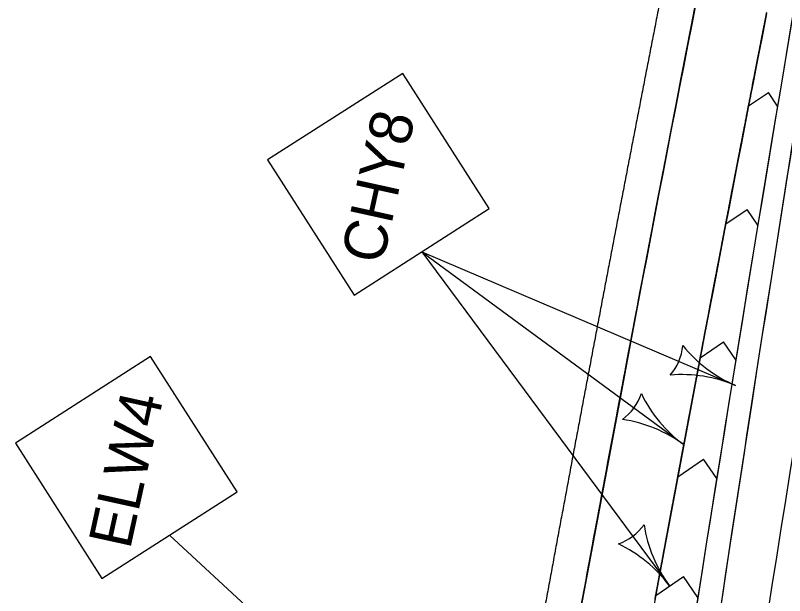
# Model space of a CAD drawing. Extents: x 14104283 to 14120882, y 8635219 to 8671666.
# Drawn here: x 14107883.7 to 14108013.1, y 8640340.4 to 8640438 of the extents above; entities that cross this region are included whole.
import ezdxf

# ---------------------------------------------------------------- set-up
doc = ezdxf.new("R2010")
doc.units = 0
for name, color, linetype in [('dsnPaintPlaceBrokenLineWhite', 7, 'Continuous'), ('dsnPaintPlaceChannelizingLaneWhite', 7, 'Continuous'), ('dsnPaintPlaceEdgeLineRightWhite', 7, 'Continuous'), ('dsnShadingPaved', 7, 'Continuous'), ('dsnStdLabel', 7, 'Continuous'), ('dsnStgShadingPrevPav', 7, 'Continuous')]:
    doc.layers.add(name, color=color, linetype=linetype)

msp = doc.modelspace()

# ---------------------------------------------------------------- linework, layer by layer
at = {"layer": 'dsnPaintPlaceBrokenLineWhite'}
msp.add_arc((14117394.14, 8638857.08), 9500, 167.610212, 171.325989, dxfattribs=at)
at = {"layer": 'dsnPaintPlaceChannelizingLaneWhite'}
for p, q in [((14108006.99, 8640422.76), (14108010.34, 8640425.01)), ((14108011.88, 8640422.72), (14108010.34, 8640425.01)), ((14108003.16, 8640402.9), (14108006.75, 8640405.34)), ((14108008.56, 8640402.67), (14108006.75, 8640405.34)), ((14107998.87, 8640380.39), (14108002.8, 8640383.07)), ((14108004.86, 8640380.03), (14108002.78, 8640383.07)), ((14107995.1, 8640360.4), (14107999.42, 8640363.36)), ((14108001.65, 8640360.1), (14107999.42, 8640363.36)), ((14107991.39, 8640340.45), (14107996.03, 8640343.65)), ((14107998.47, 8640340.1), (14107996.03, 8640343.65))]:
    msp.add_line(p, q, dxfattribs=at)
for centre, radius, start, end in [((14117394.14, 8638857.08), 9512, 169.444425, 171.325989), ((14117350.61, 8638608.07), 9518.2, 168.915826, 170.320937)]:
    msp.add_arc(centre, radius, start, end, dxfattribs=at)
at = {"layer": 'dsnPaintPlaceEdgeLineRightWhite'}
msp.add_arc((14117350.61, 8638608.07), 9530.2, 168.915826, 170.320937, dxfattribs=at)
at = {"layer": 'dsnShadingPaved'}
for centre, radius, start, end in [((14117394.14, 8638857.08), 9512, 167.610212, 171.325989), ((14117394.14, 8638857.08), 9500, 167.610212, 171.325989), ((14117350.61, 8638608.07), 9530.2, 168.915826, 170.320937), ((14117350.61, 8638608.07), 9518.2, 168.915826, 170.320937)]:
    msp.add_arc(centre, radius, start, end, dxfattribs=at)
at = {"layer": 'dsnStdLabel'}
for p, q in [((14107952.01, 8640398.19), (14107996.08, 8640365.81)), ((14107952.01, 8640398.19), (14108004.82, 8640375.74)), ((14107952.01, 8640398.19), (14107993.71, 8640342.05)), ((14107909.59, 8640350.58), (14107971.39, 8640293.53))]:
    msp.add_line(p, q, dxfattribs=at)
for points in [[(14107940.63, 8640390.92), (14107963.38, 8640405.47), (14107948.83, 8640428.21), (14107926.08, 8640413.66)], [(14107898.22, 8640343.3), (14107920.97, 8640357.85), (14107906.42, 8640380.6), (14107883.67, 8640366.05)]]:
    msp.add_lwpolyline(points, close=True, dxfattribs=at)
for centre, radius, start, end in [((14107987.11, 8640383.26), 8.86, 319.2327, 354.7011), ((14108013.8, 8640396.86), 22.95, 218.8957, 246.967), ((14107995.84, 8640354.62), 22.95, 66.9669, 95.0381), ((14107980.57, 8640377.2), 8.86, 305.9579, 341.4263), ((14108009.67, 8640384.3), 22.95, 205.6209, 233.6922), ((14107982.49, 8640347.31), 22.95, 53.6921, 81.7633), ((14107982.23, 8640357.5), 8.86, 288.8714, 324.3398), ((14108012.13, 8640355.73), 22.95, 188.5344, 216.6057), ((14107975.28, 8640328.36), 22.95, 36.6055, 64.6768)]:
    msp.add_arc(centre, radius, start, end, dxfattribs=at)
at = {"layer": 'dsnStgShadingPrevPav'}
for radius, start, end in [(9488, 167.610212, 172.222077), (9512, 169.413861, 172.222077), (9488, 169.413861, 172.222077), (9512, 170.574102, 171.702544)]:
    msp.add_arc((14117407.82, 8638919.35), radius, start, end, dxfattribs=at)
for points, degree in [([(14108040.07, 8640670.33), (14108039.11, 8640666.01), (14108035.79, 8640651.03), (14108029.85, 8640623.7), (14108025.19, 8640602.04), (14108020.26, 8640578.84), (14108015.47, 8640556.04), (14108010.72, 8640533.12), (14108006.03, 8640510.22), (14108001.39, 8640487.29), (14107996.81, 8640464.36), (14107992.28, 8640441.41), (14107987.82, 8640418.46), (14107983.4, 8640395.49), (14107979.05, 8640372.51), (14107974.75, 8640349.53), (14107970.51, 8640326.51), (14107966.33, 8640303.59), (14107962.15, 8640280.24), (14107958.29, 8640258.43), (14107953.48, 8640230.88), (14107950.9, 8640215.75), (14107950.15, 8640211.39)], 2), ([(14107956.07, 8640210.37), (14107957.38, 8640218.06), (14107960.02, 8640233.43), (14107964.04, 8640256.47), (14107968.11, 8640279.5), (14107972.24, 8640302.51), (14107976.42, 8640325.52), (14107980.66, 8640348.51), (14107984.96, 8640371.49), (14107989.32, 8640394.46), (14107993.73, 8640417.41), (14107998.19, 8640440.35), (14108002.71, 8640463.28), (14108007.29, 8640486.2), (14108011.92, 8640509.1), (14108016.61, 8640531.99), (14108021.36, 8640554.87), (14108026.16, 8640577.73), (14108031.01, 8640600.58), (14108035.93, 8640623.41), (14108040.89, 8640646.24), (14108044.25, 8640661.44), (14108045.92, 8640669.04)], 3), ([(14107995.51, 8640426.59), (14107996.26, 8640430.41), (14107997, 8640434.24), (14107997.75, 8640438.06)], 2), ([(14108010.05, 8640438.44), (14108009.9, 8640437.67), (14108009.75, 8640436.91), (14108009.6, 8640436.15)], 2), ([(14108009.6, 8640436.15), (14108009.75, 8640436.91), (14108009.9, 8640437.67), (14108010.05, 8640438.44)], 2), ([(14108009.37, 8640435), (14108009.15, 8640433.86), (14108008.93, 8640432.71), (14108008.7, 8640431.56)], 2), ([(14108008.7, 8640431.56), (14108008.93, 8640432.71), (14108009.15, 8640433.86), (14108009.37, 8640435)], 2), ([(14108009.6, 8640436.15), (14108009.52, 8640435.76), (14108009.45, 8640435.38), (14108009.37, 8640435)], 2), ([(14108009.37, 8640435), (14108009.45, 8640435.38), (14108009.52, 8640435.76), (14108009.6, 8640436.15)], 2), ([(14108008.7, 8640431.56), (14108008.63, 8640431.18), (14108008.55, 8640430.8), (14108008.48, 8640430.42)], 2), ([(14108008.48, 8640430.42), (14108008.55, 8640430.8), (14108008.63, 8640431.18), (14108008.7, 8640431.56)], 2), ([(14108008.48, 8640430.42), (14108008.4, 8640430.04), (14108008.33, 8640429.65), (14108008.26, 8640429.27)], 2), ([(14108008.26, 8640429.27), (14108008.33, 8640429.65), (14108008.4, 8640430.04), (14108008.48, 8640430.42)], 2), ([(14108008.26, 8640429.27), (14108008.18, 8640428.89), (14108008.11, 8640428.51), (14108008.03, 8640428.13)], 2), ([(14108008.03, 8640428.13), (14108008.11, 8640428.51), (14108008.18, 8640428.89), (14108008.26, 8640429.27)], 2), ([(14108008.03, 8640428.13), (14108007.29, 8640424.31), (14108006.55, 8640420.49), (14108005.81, 8640416.67)], 2), ([(14108005.81, 8640416.67), (14108006.55, 8640420.49), (14108007.29, 8640424.31), (14108008.03, 8640428.13)], 2), ([(14107995.29, 8640425.44), (14107995.37, 8640425.82), (14107995.44, 8640426.21), (14107995.51, 8640426.59)], 2), ([(14107995.07, 8640424.29), (14107995.14, 8640424.68), (14107995.22, 8640425.06), (14107995.29, 8640425.44)], 2), ([(14107994.85, 8640423.15), (14107994.92, 8640423.53), (14107994.99, 8640423.91), (14107995.07, 8640424.29)], 2), ([(14107994.4, 8640420.85), (14107994.55, 8640421.62), (14107994.7, 8640422.38), (14107994.85, 8640423.15)], 2), ([(14107994.18, 8640419.7), (14107994.25, 8640420.09), (14107994.33, 8640420.47), (14107994.4, 8640420.85)], 2), ([(14107993.73, 8640417.41), (14107993.88, 8640418.17), (14107994.03, 8640418.94), (14107994.18, 8640419.7)], 2), ([(14107992.63, 8640411.67), (14107993, 8640413.58), (14107993.36, 8640415.5), (14107993.73, 8640417.41)], 2), ([(14108005.59, 8640415.52), (14108005.36, 8640414.38), (14108005.14, 8640413.23), (14108004.92, 8640412.09)], 2), ([(14108004.92, 8640412.09), (14108005.14, 8640413.23), (14108005.36, 8640414.38), (14108005.59, 8640415.52)], 2), ([(14108005.81, 8640416.67), (14108005.73, 8640416.29), (14108005.66, 8640415.91), (14108005.59, 8640415.52)], 2), ([(14108005.59, 8640415.52), (14108005.66, 8640415.91), (14108005.73, 8640416.29), (14108005.81, 8640416.67)], 2), ([(14107991.52, 8640405.93), (14107991.89, 8640407.85), (14107992.26, 8640409.76), (14107992.63, 8640411.67)], 2), ([(14108004.92, 8640412.09), (14108004.77, 8640411.32), (14108004.63, 8640410.56), (14108004.48, 8640409.79)], 2), ([(14108004.48, 8640409.79), (14108004.63, 8640410.56), (14108004.77, 8640411.32), (14108004.92, 8640412.09)], 2), ([(14108004.48, 8640409.79), (14108004.18, 8640408.27), (14108003.89, 8640406.74), (14108003.6, 8640405.21)], 2), ([(14108003.6, 8640405.21), (14108003.89, 8640406.74), (14108004.18, 8640408.27), (14108004.48, 8640409.79)], 2), ([(14107991.3, 8640404.79), (14107991.38, 8640405.17), (14107991.45, 8640405.55), (14107991.52, 8640405.93)], 2), ([(14108003.6, 8640405.21), (14108003.3, 8640403.68), (14108003.01, 8640402.15), (14108002.72, 8640400.62)], 2), ([(14108002.72, 8640400.62), (14108003.01, 8640402.15), (14108003.3, 8640403.68), (14108003.6, 8640405.21)], 2), ([(14107990.42, 8640400.19), (14107990.72, 8640401.73), (14107991.01, 8640403.26), (14107991.3, 8640404.79)], 2), ([(14107989.54, 8640395.6), (14107989.84, 8640397.13), (14107990.13, 8640398.66), (14107990.42, 8640400.19)], 2), ([(14108002.72, 8640400.62), (14108002.28, 8640398.33), (14108001.84, 8640396.04), (14108001.4, 8640393.74)], 2), ([(14108001.4, 8640393.74), (14108001.84, 8640396.04), (14108002.28, 8640398.33), (14108002.72, 8640400.62)], 2), ([(14107989.33, 8640394.45), (14107989.4, 8640394.84), (14107989.47, 8640395.22), (14107989.54, 8640395.6)], 2), ([(14107989.11, 8640393.31), (14107989.18, 8640393.69), (14107989.25, 8640394.07), (14107989.33, 8640394.45)], 2), ([(14108001.4, 8640393.74), (14108001.33, 8640393.36), (14108001.25, 8640392.98), (14108001.18, 8640392.6)], 2), ([(14108001.18, 8640392.6), (14108001.25, 8640392.98), (14108001.33, 8640393.36), (14108001.4, 8640393.74)], 2), ([(14107988.23, 8640388.71), (14107988.52, 8640390.25), (14107988.81, 8640391.78), (14107989.11, 8640393.31)], 2), ([(14108001.18, 8640392.6), (14108001.03, 8640391.83), (14108000.89, 8640391.07), (14108000.74, 8640390.3)], 2), ([(14108000.74, 8640390.3), (14108000.89, 8640391.07), (14108001.03, 8640391.83), (14108001.18, 8640392.6)], 2), ([(14108000.74, 8640390.3), (14108000.6, 8640389.54), (14108000.45, 8640388.78), (14108000.31, 8640388.01)], 2), ([(14108000.31, 8640388.01), (14108000.45, 8640388.78), (14108000.6, 8640389.54), (14108000.74, 8640390.3)], 2), ([(14107987.58, 8640385.27), (14107987.79, 8640386.42), (14107988.01, 8640387.57), (14107988.23, 8640388.71)], 2), ([(14108000.31, 8640388.01), (14108000.02, 8640386.48), (14107999.72, 8640384.95), (14107999.43, 8640383.42)], 2), ([(14107999.43, 8640383.42), (14107999.72, 8640384.95), (14108000.02, 8640386.48), (14108000.31, 8640388.01)], 2), ([(14107987.36, 8640384.12), (14107987.43, 8640384.5), (14107987.5, 8640384.89), (14107987.58, 8640385.27)], 2), ([(14107986.92, 8640381.82), (14107987.07, 8640382.59), (14107987.21, 8640383.36), (14107987.36, 8640384.12)], 2), ([(14107999.43, 8640383.42), (14107999, 8640381.13), (14107998.56, 8640378.84), (14107998.13, 8640376.54)], 2), ([(14107998.13, 8640376.54), (14107998.56, 8640378.84), (14107999, 8640381.13), (14107999.43, 8640383.42)], 2), ([(14107986.05, 8640377.23), (14107986.34, 8640378.76), (14107986.63, 8640380.29), (14107986.92, 8640381.82)], 2), ([(14107985.84, 8640376.08), (14107985.91, 8640376.46), (14107985.98, 8640376.85), (14107986.05, 8640377.23)], 2), ([(14107985.19, 8640372.64), (14107985.4, 8640373.78), (14107985.62, 8640374.93), (14107985.84, 8640376.08)], 2), ([(14107998.13, 8640376.54), (14107998.06, 8640376.16), (14107997.99, 8640375.78), (14107997.91, 8640375.4)], 2), ([(14107997.91, 8640375.4), (14107997.99, 8640375.78), (14107998.06, 8640376.16), (14107998.13, 8640376.54)], 2), ([(14107997.91, 8640375.4), (14107997.55, 8640373.48), (14107997.19, 8640371.57), (14107996.83, 8640369.66)], 2), ([(14107996.83, 8640369.66), (14107997.19, 8640371.57), (14107997.55, 8640373.48), (14107997.91, 8640375.4)], 2), ([(14107984.97, 8640371.49), (14107985.04, 8640371.87), (14107985.12, 8640372.25), (14107985.19, 8640372.64)], 2), ([(14107984.32, 8640368.04), (14107984.54, 8640369.19), (14107984.76, 8640370.34), (14107984.97, 8640371.49)], 2), ([(14107996.83, 8640369.66), (14107996.62, 8640368.51), (14107996.4, 8640367.37), (14107996.18, 8640366.22)], 2), ([(14107996.18, 8640366.22), (14107996.4, 8640367.37), (14107996.62, 8640368.51), (14107996.83, 8640369.66)], 2), ([(14107983.25, 8640362.3), (14107983.6, 8640364.21), (14107983.96, 8640366.13), (14107984.32, 8640368.04)], 2), ([(14107995.97, 8640365.07), (14107995.9, 8640364.69), (14107995.82, 8640364.31), (14107995.75, 8640363.92)], 2), ([(14107995.75, 8640363.92), (14107995.82, 8640364.31), (14107995.9, 8640364.69), (14107995.97, 8640365.07)], 2), ([(14107996.18, 8640366.22), (14107996.11, 8640365.84), (14107996.04, 8640365.45), (14107995.97, 8640365.07)], 2), ([(14107995.97, 8640365.07), (14107996.04, 8640365.45), (14107996.11, 8640365.84), (14107996.18, 8640366.22)], 2), ([(14107995.75, 8640363.92), (14107995.68, 8640363.54), (14107995.61, 8640363.16), (14107995.54, 8640362.78)], 2), ([(14107995.54, 8640362.78), (14107995.61, 8640363.16), (14107995.68, 8640363.54), (14107995.75, 8640363.92)], 2), ([(14107995.54, 8640362.78), (14107995.32, 8640361.63), (14107995.11, 8640360.48), (14107994.89, 8640359.33)], 2), ([(14107994.89, 8640359.33), (14107995.11, 8640360.48), (14107995.32, 8640361.63), (14107995.54, 8640362.78)], 2), ([(14107982.39, 8640357.7), (14107982.67, 8640359.23), (14107982.96, 8640360.76), (14107983.25, 8640362.3)], 2), ([(14107994.89, 8640359.33), (14107994.68, 8640358.19), (14107994.46, 8640357.04), (14107994.25, 8640355.89)], 2), ([(14107994.25, 8640355.89), (14107994.46, 8640357.04), (14107994.68, 8640358.19), (14107994.89, 8640359.33)], 2), ([(14107981.96, 8640355.4), (14107982.1, 8640356.17), (14107982.24, 8640356.93), (14107982.39, 8640357.7)], 2), ([(14107981.74, 8640354.25), (14107981.81, 8640354.64), (14107981.89, 8640355.02), (14107981.96, 8640355.4)], 2), ([(14107994.03, 8640354.74), (14107993.96, 8640354.36), (14107993.89, 8640353.98), (14107993.82, 8640353.6)], 2), ([(14107993.82, 8640353.6), (14107993.89, 8640353.98), (14107993.96, 8640354.36), (14107994.03, 8640354.74)], 2), ([(14107994.25, 8640355.89), (14107994.18, 8640355.51), (14107994.11, 8640355.13), (14107994.03, 8640354.74)], 2), ([(14107994.03, 8640354.74), (14107994.11, 8640355.13), (14107994.18, 8640355.51), (14107994.25, 8640355.89)], 2), ([(14107981.53, 8640353.1), (14107981.6, 8640353.49), (14107981.67, 8640353.87), (14107981.74, 8640354.25)], 2), ([(14107993.82, 8640353.6), (14107993.75, 8640353.21), (14107993.68, 8640352.83), (14107993.61, 8640352.45)], 2), ([(14107993.61, 8640352.45), (14107993.68, 8640352.83), (14107993.75, 8640353.21), (14107993.82, 8640353.6)], 2), ([(14107981.1, 8640350.81), (14107981.24, 8640351.57), (14107981.39, 8640352.34), (14107981.53, 8640353.1)], 2), ([(14107993.61, 8640352.45), (14107993.53, 8640352.06), (14107993.46, 8640351.68), (14107993.39, 8640351.3)], 2), ([(14107993.39, 8640351.3), (14107993.46, 8640351.68), (14107993.53, 8640352.06), (14107993.61, 8640352.45)], 2), ([(14107993.39, 8640351.3), (14107993.11, 8640349.77), (14107992.82, 8640348.24), (14107992.54, 8640346.71)], 2), ([(14107992.54, 8640346.71), (14107992.82, 8640348.24), (14107993.11, 8640349.77), (14107993.39, 8640351.3)], 2), ([(14107980.67, 8640348.51), (14107980.74, 8640348.89), (14107980.82, 8640349.27), (14107980.89, 8640349.66)], 2), ([(14107980.89, 8640349.66), (14107980.96, 8640350.04), (14107981.03, 8640350.42), (14107981.1, 8640350.81)], 2), ([(14107980.46, 8640347.36), (14107980.53, 8640347.74), (14107980.6, 8640348.12), (14107980.67, 8640348.51)], 2), ([(14107979.4, 8640341.61), (14107979.75, 8640343.53), (14107980.1, 8640345.44), (14107980.46, 8640347.36)], 2), ([(14107992.54, 8640346.71), (14107992.11, 8640344.41), (14107991.69, 8640342.12), (14107991.26, 8640339.82)], 2), ([(14107991.26, 8640339.82), (14107991.69, 8640342.12), (14107992.11, 8640344.41), (14107992.54, 8640346.71)], 2), ([(14107978.33, 8640335.86), (14107978.69, 8640337.78), (14107979.04, 8640339.7), (14107979.4, 8640341.61)], 2)]:
    msp.add_open_spline(points, degree=degree, dxfattribs=at)

# ---------------------------------------------------------------- texts
at = {"layer": 'dsnStdLabel'}
for s, p in [('CHY8', (14107945.42, 8640395.9)), ('ELW4', (14107902.95, 8640348.04))]:
    msp.add_text(s, height=7.2, rotation=77.6078, dxfattribs=at).set_placement(p)

doc.saveas('drawing.dxf')
